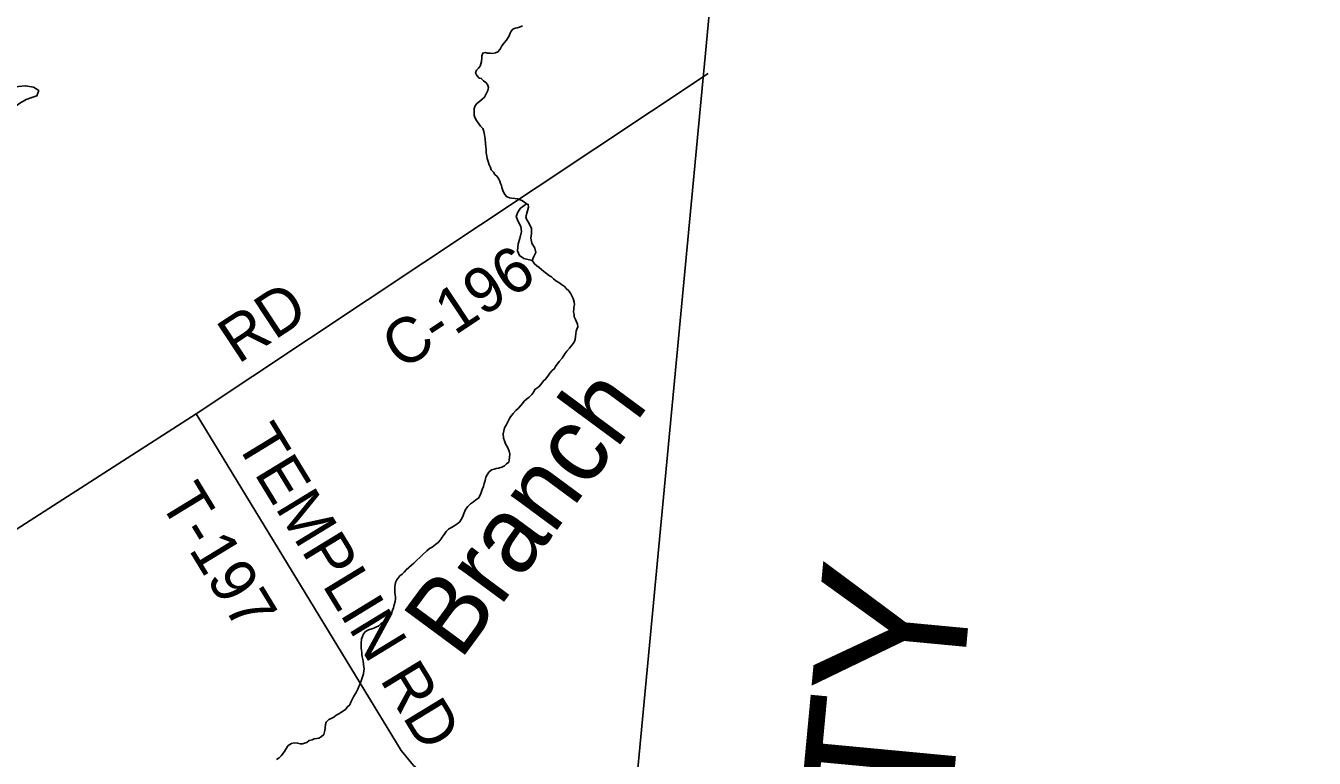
# Model space of a CAD drawing. Extents: x 1310247 to 1664935, y 284496 to 704931.
# Drawn here: x 1540499 to 1549068, y 491123 to 495991 of the extents above; entities that cross this region are included whole.
import ezdxf

# ---------------------------------------------------------------- set-up
doc = ezdxf.new("R2010")
doc.units = 0
for name, color, linetype in [('GM_X_Adjacent_County', 7, 'Continuous'), ('GM_X_Adjacent_County_Text', 7, 'Continuous'), ('GM_X_County_Road_Text', 7, 'Continuous'), ('GM_X_County_Subdivision_Text', 7, 'Continuous'), ('GM_X_Minor_Lake', 7, 'Continuous'), ('GM_X_Minor_Lake_Text', 7, 'Continuous'), ('GM_X_Minor_River', 7, 'Continuous'), ('GM_X_Minor_River_Text', 7, 'Continuous'), ('GM_X_Township', 7, 'Continuous'), ('GM_X_Township_Road', 7, 'Continuous'), ('GM_X_Township_Subdivision', 7, 'Continuous')]:
    doc.layers.add(name, color=color, linetype=linetype)

msp = doc.modelspace()

# ---------------------------------------------------------------- linework, layer by layer
at = {"layer": 'GM_X_Adjacent_County'}
msp.add_lwpolyline([(1539239.6, 496432), (1543391.6, 498392.7), (1545352.6, 499330.6), (1545078, 496425), (1545013, 495737.5), (1545002.2, 495623.2), (1544428.8, 489554.2), (1544211.7, 487255.6), (1544122.7, 486001.5), (1543861.4, 483361.9), (1543818, 482923.1), (1543135.8, 476031.3)], dxfattribs=at)
at = {"layer": 'GM_X_Adjacent_County_Text'}
msp.add_lwpolyline([(1543135.8, 476031.3), (1543818, 482923.1), (1543861.4, 483361.9), (1544122.7, 486001.5), (1544211.7, 487255.6), (1544428.8, 489554.2), (1545002.2, 495623.2), (1545013, 495737.5), (1545078, 496425), (1545352.6, 499330.6), (1545798, 504043.7), (1545822.1, 504298.4), (1546297.7, 509605.7), (1546686.4, 513989.1), (1546925.5, 516687), (1547324.3, 521188.2), (1547463.3, 522758.3), (1547776.9, 526306), (1548052.5, 529426.3), (1548058.9, 529499.7), (1548609.4, 535719), (1548703.3, 536778.9), (1549067.9, 540794.2)], dxfattribs=at)
at = {"layer": 'GM_X_County_Road_Text'}
msp.add_lwpolyline([(1545038.4, 495674), (1541632.4, 493412.9), (1539973.5, 492348.4), (1539652, 492142.1), (1539479.6, 492034.5), (1539352.1, 491972.3), (1539081.9, 491908.3), (1538809.9, 491852.4), (1538688.8, 491814.2), (1536564.9, 490615.9)], dxfattribs=at)
at = {"layer": 'GM_X_County_Subdivision_Text'}
msp.add_lwpolyline([(1541632.4, 493412.9), (1542995.2, 491173.8), (1543078, 491074.2), (1543248.5, 490933.2), (1543983, 490384.4), (1544048.2, 490311.2), (1544158.1, 490147.1), (1544456.1, 489526.1)], dxfattribs=at)
at = {"layer": 'GM_X_Minor_River'}
for points in [[(1540073.2, 495015.8), (1540151.9, 495020.2), (1540163.1, 495076.2), (1540176.2, 495128.2), (1540207.5, 495179.8), (1540238.6, 495223.4), (1540282.1, 495280.8), (1540339.6, 495335.9), (1540382.7, 495375.2), (1540405.6, 495410.9), (1540426.6, 495452.7), (1540459.3, 495476.1), (1540502.2, 495501.4), (1540540.7, 495514.7), (1540573.2, 495526.1), (1540586, 495560), (1540550.1, 495582.8), (1540497.9, 495591.8), (1540426.6, 495585.1)], [(1543828.9, 494808.3), (1543804.4, 494790.7), (1543790, 494778.9), (1543771.4, 494753.2), (1543760.7, 494723.3), (1543774.2, 494690.9), (1543791.6, 494656.4), (1543795, 494624.2), (1543786, 494576.2), (1543773.2, 494542.3), (1543770.3, 494496.2), (1543783.8, 494463.8), (1543811.6, 494443.2), (1543867.8, 494432)], [(1543867.8, 494432), (1543876.3, 494454), (1543891, 494483.8), (1543885.6, 494514), (1543864, 494546.6), (1543858.6, 494578.8), (1543863.3, 494610.8), (1543861.9, 494643), (1543846.5, 494677.4), (1543828.9, 494705.9), (1543825.2, 494722), (1543836, 494762), (1543842.6, 494786), (1543840.9, 494804), (1543828.9, 494808.3)]]:
    msp.add_lwpolyline(points, dxfattribs=at)
at = {"layer": 'GM_X_Minor_River_Text'}
for points in [[(1543828.9, 494808.3), (1543815, 494819.3), (1543799.2, 494829.7), (1543783.3, 494836.1), (1543769.3, 494840.5), (1543751.3, 494842.9), (1543729.3, 494845.5), (1543715.3, 494847.8), (1543695.4, 494856.3), (1543679.8, 494876.8), (1543672.3, 494897), (1543664.7, 494915.2), (1543663.1, 494929.3), (1543657.4, 494943.5), (1543651.7, 494957.7), (1543646, 494971.8), (1543634.4, 494988.2), (1543618.7, 495002.6), (1543609, 495016.9), (1543593.3, 495033.3), (1543589.7, 495049.5), (1543580.1, 495067.7), (1543574.7, 495089.9), (1543567.1, 495108.2), (1543565.5, 495124.3), (1543562, 495146.4), (1543560.6, 495168.5), (1543559, 495186.6), (1543557.5, 495206.7), (1543554.3, 495238.9), (1543552.6, 495253), (1543551, 495267.1), (1543545.5, 495287.3), (1543537.9, 495307.5), (1543524.3, 495323.9), (1543512.6, 495340.2), (1543497.1, 495360.6), (1543485.5, 495381), (1543481.9, 495397.1), (1543480.5, 495419.2), (1543481, 495441.3), (1543487.5, 495459.2), (1543499.9, 495475), (1543516.4, 495488.6), (1543534.8, 495502.2), (1543549.2, 495515.9), (1543561.8, 495537.7), (1543572.4, 495561.5), (1543576.9, 495581.4), (1543569.4, 495599.7), (1543559.7, 495614), (1543543.9, 495624.4), (1543528.2, 495640.8), (1543514.2, 495643.1), (1543498.5, 495659.6), (1543491, 495677.8), (1543497.4, 495695.7), (1543509.8, 495709.4), (1543520.2, 495723.2), (1543524.6, 495737.2), (1543529, 495753.1), (1543531.6, 495777.1), (1543532, 495791.2), (1543538.5, 495809.1), (1543556.6, 495812.6), (1543570.6, 495808.3), (1543586.6, 495807.9), (1543602.7, 495807.5), (1543622.9, 495811), (1543639.1, 495816.7), (1543653.6, 495834.4), (1543666.2, 495858.2), (1543680.8, 495877.9), (1543695.3, 495895.6), (1543714.1, 495923.2), (1543720.5, 495941.1), (1543726.9, 495955), (1543739.3, 495968.7), (1543753.5, 495974.4), (1543767.6, 495976.1), (1543783.8, 495981.7), (1543802.2, 495991.3)], [(1544097.5, 493827.4), (1544116.1, 493849), (1544132.7, 493870.7), (1544145.2, 493888.5), (1544153.7, 493906.3), (1544156.2, 493926.3), (1544156.7, 493944.3), (1544159.1, 493960.3), (1544163.5, 493974.3), (1544169.9, 493990.2), (1544168.3, 494008.3), (1544162.6, 494022.4), (1544155, 494038.7), (1544147.4, 494056.9), (1544145.8, 494073), (1544142.2, 494089.1), (1544144.7, 494107.1), (1544145, 494121.2), (1544147.5, 494139.2), (1544145.8, 494153.3), (1544140.4, 494177.5), (1544132.7, 494191.7), (1544125.2, 494209.9), (1544111.6, 494228.3), (1544093.9, 494244.8), (1544082.2, 494259.1), (1544062.4, 494271.6), (1544044.7, 494284.1), (1544024.9, 494296.6), (1544009.1, 494309), (1543995.4, 494321.4), (1543981.5, 494329.8), (1543961.8, 494344.3), (1543944.1, 494358.8), (1543928.3, 494371.2), (1543914.6, 494383.5), (1543898.8, 494396), (1543883, 494408.4), (1543867.8, 494432)], [(1542903.9, 492050.5), (1542916.6, 492074.3), (1542930.9, 492086), (1542937.5, 492107.9), (1542943.9, 492121.8), (1542948.4, 492141.7), (1542955, 492165.6), (1542957.4, 492179.6), (1542957.7, 492193.7), (1542956.1, 492209.8), (1542954.5, 492223.8), (1542953, 492243.9), (1542953.4, 492262), (1542958.1, 492290), (1542966.7, 492309.8), (1542987.4, 492335.4), (1543001.7, 492347.1), (1543016.1, 492360.8), (1543028.5, 492374.5), (1543047, 492390.1), (1543063.5, 492405.8), (1543079.9, 492419.4), (1543100.5, 492439), (1543121, 492456.6), (1543139.6, 492478.2), (1543166.3, 492501.6), (1543184.8, 492517.2), (1543201.1, 492526.9), (1543223.6, 492544.4), (1543242, 492556), (1543256.5, 492573.7), (1543269, 492591.4), (1543281.5, 492609.2), (1543296.1, 492630.9), (1543310.5, 492644.6), (1543326.8, 492654.2), (1543345.2, 492665.8), (1543367.7, 492681.3), (1543386.1, 492694.9), (1543394.5, 492710.8), (1543402.9, 492724.6), (1543413.7, 492754.5), (1543424.3, 492776.3), (1543438.9, 492796), (1543457.4, 492813.6), (1543475.8, 492827.2), (1543492.2, 492840.8), (1543510.6, 492852.4), (1543523.2, 492876.2), (1543534.1, 492908), (1543542.7, 492929.9), (1543547.1, 492947.9), (1543553.7, 492967.8), (1543558.3, 492991.7), (1543566.7, 493007.6), (1543579.2, 493023.3), (1543597.6, 493038.9), (1543613.8, 493044.6), (1543628, 493048.2), (1543644.2, 493051.8), (1543664.4, 493057.4), (1543682.7, 493067), (1543697.1, 493078.7), (1543711.4, 493090.4), (1543713.8, 493104.3), (1543716.3, 493124.3), (1543718.8, 493144.3), (1543713.3, 493164.5), (1543703.9, 493190.9), (1543690.4, 493213.2), (1543682.8, 493231.5), (1543677.2, 493249.7), (1543674, 493279.9), (1543683, 493317.8), (1543693.5, 493335.6), (1543702, 493355.4), (1543714.6, 493377.2), (1543723, 493393), (1543739.6, 493414.7), (1543758.2, 493434.3), (1543776.7, 493449.9), (1543801.6, 493481.4), (1543814, 493495.2), (1543830.4, 493508.8), (1543846.8, 493522.5), (1543865.3, 493540.1), (1543877.8, 493557.8), (1543884.2, 493573.7), (1543910.8, 493591.1), (1543925.2, 493606.8), (1543941.9, 493630.5), (1543956.3, 493642.2), (1543970.8, 493661.9), (1543985.4, 493681.6), (1543999.9, 493699.3), (1544016.3, 493713), (1544022.7, 493726.9), (1544047.6, 493760.4), (1544066.2, 493782), (1544085, 493809.6), (1544097.5, 493827.4)], [(1542167.4, 491115.3), (1542183.7, 491126.9), (1542198.1, 491138.6), (1542220.9, 491168.1), (1542229.3, 491184), (1542244, 491207.7), (1542266.4, 491221.2), (1542286.6, 491224.7), (1542306.7, 491224.2), (1542324.7, 491219.8), (1542338.7, 491219.5), (1542352.9, 491223.1), (1542369.1, 491228.8), (1542383.4, 491240.5), (1542403.7, 491246), (1542417.9, 491251.7), (1542434, 491253.3), (1542448.1, 491257), (1542464.4, 491264.6), (1542480.8, 491280.2), (1542487.6, 491308.2), (1542489.9, 491322.2), (1542492.6, 491348.2), (1542497, 491362.1), (1542515.5, 491379.7), (1542529.7, 491387.4), (1542548.1, 491397), (1542564.4, 491408.6), (1542580.7, 491418.3), (1542595, 491426), (1542613.4, 491437.5), (1542627.7, 491449.2), (1542636.1, 491463.1), (1542654.6, 491478.7), (1542661, 491496.6), (1542678, 491530.3), (1542698.9, 491563.9), (1542707.4, 491581.8), (1542713.8, 491599.6), (1542720.2, 491613.5), (1542731, 491643.4), (1542739.5, 491663.2), (1542746.1, 491683.1), (1542748.6, 491703.1), (1542748.9, 491717.2), (1542747.3, 491731.3), (1542745.6, 491745.3), (1542742.2, 491771.5), (1542736.9, 491797.7), (1542735.2, 491811.8), (1542733.6, 491825.9), (1542731.9, 491840), (1542730.3, 491856.1), (1542729.1, 491886.2), (1542731.8, 491916.2), (1542738.2, 491932.1), (1542744.7, 491950), (1542759.2, 491965.7), (1542777.5, 491977.3), (1542799.8, 491982.8), (1542814, 491988.5), (1542828.2, 491994.1), (1542846.5, 492003.7), (1542860.9, 492015.4), (1542877.3, 492029.1), (1542891.5, 492036.8), (1542903.9, 492050.5)]]:
    msp.add_lwpolyline(points, dxfattribs=at)
at = {"layer": 'GM_X_Township'}
msp.add_lwpolyline([(1549067.9, 540794.2), (1548703.3, 536778.9), (1548609.4, 535719), (1548058.9, 529499.7), (1548052.5, 529426.3), (1547776.9, 526306), (1547463.3, 522758.3), (1547324.3, 521188.2), (1546925.5, 516687), (1546686.4, 513989.1), (1546297.7, 509605.7), (1545822.1, 504298.4), (1545798, 504043.7), (1545352.6, 499330.6), (1545078, 496425), (1545013, 495737.5), (1545002.2, 495623.2), (1544428.8, 489554.2), (1544211.7, 487255.6), (1544122.7, 486001.5), (1543861.4, 483361.9), (1543818, 482923.1), (1543135.8, 476031.3)], dxfattribs=at)

# ---------------------------------------------------------------- texts
at = {"layer": 'GM_X_Minor_Lake'}
msp.add_text('CLINTON COUNTY', height=1000, rotation=84.61794, dxfattribs=at).set_placement((1545686.5, 480535.3))
at = {"layer": 'GM_X_Minor_Lake_Text'}
msp.add_text('Branch', height=500, rotation=53.56313, dxfattribs=at).set_placement((1543387.6, 491766.3))
at = {"layer": 'GM_X_Township_Road'}
for s, rotation, p in [('C-196', 33.61303, (1542999.8, 493695.3)), ('RD', 33.41621, (1541911.5, 493739.4))]:
    msp.add_text(s, height=300, rotation=rotation, dxfattribs=at).set_placement(p)
at = {"layer": 'GM_X_Township_Subdivision'}
for s, rotation, p in [('TEMPLIN RD', 301.35856, (1541887.1, 493226.6)), ('T-197', 301.34938, (1541382.2, 492833.3))]:
    msp.add_text(s, height=300, rotation=rotation, dxfattribs=at).set_placement(p)

doc.saveas('drawing.dxf')
